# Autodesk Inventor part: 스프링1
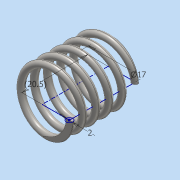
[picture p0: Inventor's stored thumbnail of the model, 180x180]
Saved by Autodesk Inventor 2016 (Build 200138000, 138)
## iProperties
Created: 2019-11
Part Number: 스프링1
Material: 스테인레스 스틸
Document SubType Name: Modeling
Designer: user
Density: 8 g/cm^3
Appearance: 반연마
Mass: 6.57569 g
Surface Area: 16.7192 cm^2
Volume: 0.821961 cm^3
Author: user
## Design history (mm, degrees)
sketch "스케치1"
  geometry: L1 (0, 0)-(8.5, 0); L2 (8.5, 0)-(8.5, 20.5); L3 (8.5, 20.5)-(0, 20.5); L4 (0, 20.5)-(0, 0); C1 r 1 at (8.5, 0)
  constraints: 8 end point, 2 parallel, 1 centre point, 1 coincident, 1 horizontal, 1 perpendicular
  dimensions: "d0" = 17 diameter of L2 L4; "d1" = 20.5 distance between parallel lines of L1 L3 (derived); "d2" = 2 diameter of C1
feature "코일1" sketch "스케치1" pitch "d3" = 10; turns "d5" = 5; dims "d4" = 20.5 (= d1), "d6" = 0, angle "d7" = 90 deg, angle "d8" = 90 deg, "d9" = 0, "d10" = 0
sketch "스케치2"
  geometry: L1 (-11.228, 0)-(11.228, 0); L2 (11.228, 0)-(11.228, 20.5); L3 (11.228, 20.5)-(-11.228, 20.5); L4 (-11.228, 20.5)-(-11.228, 0); 2 further points
  constraints: 8 end point, 2 parallel, 1 coincident, 1 horizontal, 1 midpoint, 1 perpendicular
  dimensions: "d11" = 20.5 distance between parallel lines of L1 L3 (= d1); "d12" = 22.45649 distance between parallel lines of L2 L4
extrude "돌출1" sketch "스케치2" stored distance "d13" = 42.25; taper "d14" = 0 deg
node "솔리드1"
